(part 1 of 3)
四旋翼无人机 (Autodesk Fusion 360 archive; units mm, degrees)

design "基础版支架" references "摄像头", "舵机控制电板", "遥控天线", "画面图传电板", "摄像头与遥控接收电板", "螺旋桨"
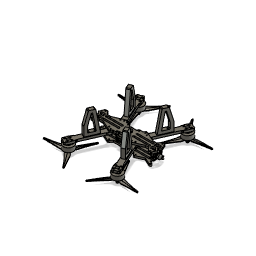
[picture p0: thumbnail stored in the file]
sketch "草图1" plane through (0, 0, 0) normal (0, 1, 0) x axis (1, 0, 0)
  line L1 (-87.5, 17.5) -> (87.5, 17.5)
  line L2 (-87.5, -17.5) -> (-87.5, 17.5)
  line L3 (87.5, -17.5) -> (-87.5, -17.5)
  line L4 (87.5, 17.5) -> (87.5, -17.5)
  line L5 (-87.5, -17.5) -> (87.5, 17.5)
  line L6 (87.5, -17.5) -> (-87.5, 17.5)
  line L7 (-15, 15) -> (15, 15)
  line L8 (-15, -15) -> (-15, 15)
  line L9 (15, -15) -> (-15, -15)
  line L10 (15, 15) -> (15, -15)
  line L11 (-15, -15) -> (15, 15)
  line L12 (15, -15) -> (-15, 15)
  line L13 (27.2129, 24) -> (22, 17.5)
  line L14 (42, 17.5) -> (27.2129, 24)
  line L15 (12, 17.5) -> (0, 17.5)
  line L16 (12, 12) -> (12, 17.5)
  line L17 (0, 12) -> (12, 12)
  line L18 (0, 17.5) -> (0, 12)
  line L19 (97, 0) -> (0, 0)
  line L20 (97, 40) -> (97, 0)
  line L21 (0, 40) -> (97, 40)
  line L22 (0, 0) -> (0, 40)
  line L23 (57.9246, 10.5) -> (42, 17.5)
  line L24 (67.6263, 10.5) -> (57.9246, 10.5)
  line L25 (73.5, 17.5) -> (67.6263, 10.5)
  line L26 (87.5, 6) -> (82.5, 17.5)
  line L27 (82.5, 1.8045) -> (87.5, 6)
  line L28 (82.5, 0) -> (82.5, 1.8045)
  circle C1 centre (-15, 15) radius 1.5
  circle C2 centre (-15, -15) radius 1.5
  circle C3 centre (15, -15) radius 1.5
  circle C4 centre (15, 15) radius 1.5
  point P6 (0, 0)
  point P1 (0, 0)
  point P11 (0, 0)
  point P8 (-15, 15)
  point P12 (-15, 15)
  point P16 (22, 17.5)
  point P18 (42, 17.5)
  point P21 (12, 12)
  point P19 (0, 17.5)
  point P23 (0, 0)
  point P29 (73.5, 17.5)
  point P30 (82.5, 17.5)
  point P31 (87.5, 6)
  point P33 (82.5, 0)
  point P2 (87.5, 17.5)
  point P3 (-87.5, 17.5)
  point P5 (87.5, -17.5)
  point P9 (-15, -15)
  point P10 (15, -15)
  point P22 (0, 12)
  point P17 (27.2129, 24)
  point P32 (82.5, 1.8045)
  horizontal L1
  perpendicular L1 L2
  parallel L1 L3
  parallel L2 L4
  coincident L5 P6
  coincident L6 P6
  coincident P1 P6
  horizontal L7
  perpendicular L7 L8
  parallel L7 L9
  parallel L8 L10
  coincident L11 P11
  coincident L12 P11
  coincident P1 P11
  coincident P8 P12
  coincident L1 P16
  coincident L1 P18
  horizontal L15
  vertical L16
  horizontal L17
  vertical L18
  coincident L11 P21
  midpoint L1 P19
  horizontal L19
  vertical L20
  horizontal L21
  vertical L22
  coincident P6 P23
  parallel L14 L23
  coincident L1 P29
  parallel L1 L24
  coincident L1 P30
  coincident L4 P31
  coincident L19 P33
  perpendicular L19 L28
  dimension "d1" distance P2 P3 = 175
  dimension "d2" distance P2 P5 = 35
  dimension "d3" distance P9 P10 = 30
  dimension "d4" distance P8 P9 = 30
  dimension "d5" diameter C1 = 3
  dimension "d8" angle L13 L14 = 105
  dimension "d9" distance P21 P22 = 12
  dimension "d10" distance P16 L22 = 22
  dimension "d11" distance P16 P18 = 20
  dimension "d12" distance L1 P17 = 6.5
  dimension "d13" distance L19 L24 = 10.5
  dimension "d14" angle L24 L25 = 130
  dimension "d15" distance L4 P29 = 14
  dimension "d16" distance P2 P30 = 5
  dimension "d17" distance L19 P31 = 6
  dimension "d18" distance L4 P32 = 5
  dimension "d19" angle L27 L28 = 130
  dimension "d7" C-Pattern1-Angle = 360
extrude "拉伸1" new body sketch "草图1" profile of L1 C4 L13 L14 L16 L17 L19 L22 L23 L24 L25 L26 L27 L28 along normal blind 2
sketch "草图2" plane through (0, 2, 0) normal (0, 1, 0) x axis (-1, 0, 0)
  line L1 (-73.5, -17.5) -> (-82.5, -17.5)
  line L2 (-67.6263, -10.5) -> (-73.5, -17.5)
  line L3 (-57.9246, -10.5) -> (-67.6263, -10.5)
  line L4 (-27.2129, -24) -> (-57.9246, -10.5)
  line L5 (-22, -17.5) -> (-27.2129, -24)
  line L6 (-12, -17.5) -> (-22, -17.5)
  line L7 (-12, -12) -> (-12, -17.5)
  line L8 (0, -12) -> (-12, -12)
  line L9 (0, 0) -> (0, -12)
  line L10 (-82.5, 0) -> (0, 0)
  line L11 (-82.5, -1.8045) -> (-82.5, 0)
  line L12 (-87.5, -6) -> (-82.5, -1.8045)
  line L13 (-82.5, -17.5) -> (-87.5, -6)
  circle C1 centre (-15, -15) radius 1.5
  circle C2 centre (-29, -18.845) radius 1.5
  circle C3 centre (-36.3237, -15.6258) radius 1.5
  point P16 (-29, -18.845)
  point P8 (-22, -17.5)
  point P17 (-36.3237, -15.6258)
  dimension "d22" diameter C2 = 3
  dimension "d23" diameter C3 = 3
  dimension "d24" distance L4 P16 = 4
  dimension "d25" distance P8 P16 = 7
  dimension "d26" distance L4 P17 = 4 (= "d24")
  dimension "d27" distance P16 P17 = 8
extrude "拉伸2" cut sketch "草图2" profile of C2 C3 against normal blind 5
sketch "草图3" plane through (0, 0, 0) normal (0, -1, 0) x axis (1, 0, 0)
  line L1 (82.5, -17.5) -> (73.5, -17.5)
  line L2 (87.5, -6) -> (82.5, -17.5)
  line L3 (82.5, -1.8045) -> (87.5, -6)
  line L4 (82.5, 0) -> (82.5, -1.8045)
  line L5 (0, 0) -> (82.5, 0)
  line L6 (0, -12) -> (0, 0)
  line L7 (12, -12) -> (0, -12)
  line L8 (12, -17.5) -> (12, -12)
  line L9 (22, -17.5) -> (12, -17.5)
  line L10 (27.2129, -24) -> (22, -17.5)
  line L11 (57.9246, -10.5) -> (27.2129, -24)
  line L12 (67.6263, -10.5) -> (57.9246, -10.5)
  line L13 (73.5, -17.5) -> (67.6263, -10.5)
  line L14 (64.3853, -7) -> (20, -7)
  line L15 (20, -3) -> (64.3853, -3)
  line L16 (64.3853, -5) -> (20, -5)
  circle C1 centre (29, -18.845) radius 1.5
  circle C2 centre (36.3237, -15.6258) radius 1.5
  circle C3 centre (15, -15) radius 1.5
  arc A1 centre (64.3853, -5) radius 2 clockwise from (64.3853, -3) to (64.3853, -7)
  arc A2 centre (20, -5) radius 2 clockwise from (20, -7) to (20, -3)
  tangent L14 A1
  tangent A1 L15
  parallel L14 L15
  tangent L15 A2
  tangent L14 A2
  parallel L5 L16
extrude "拉伸3" cut sketch "草图3" profile of L14 A1 L15 A2 against normal blind 8
sketch "草图4" plane through (0, 0, 0) normal (0, -1, 0) x axis (1, 0, 0)
  line L1 (20, -7) -> (64.3853, -7)
  line L2 (64.3853, -3) -> (20, -3)
  line L3 (82.5, -17.5) -> (73.5, -17.5)
  line L4 (87.5, -6) -> (82.5, -17.5)
  line L5 (82.5, -1.8045) -> (87.5, -6)
  line L6 (82.5, 0) -> (82.5, -1.8045)
  line L7 (0, 0) -> (82.5, 0)
  line L8 (0, -12) -> (0, 0)
  line L9 (12, -12) -> (0, -12)
  line L10 (12, -17.5) -> (12, -12)
  line L11 (22, -17.5) -> (12, -17.5)
  line L12 (27.2129, -24) -> (22, -17.5)
  line L13 (57.9246, -10.5) -> (27.2129, -24)
  line L14 (67.6263, -10.5) -> (57.9246, -10.5)
  line L15 (73.5, -17.5) -> (67.6263, -10.5)
  line L16 (70, -7.106) -> (70, -2)
  line L17 (72.4284, -10) -> (70, -7.106)
  line L18 (81.3992, -10) -> (72.4284, -10)
  line L19 (82.6408, -7.1443) -> (81.3992, -10)
  line L20 (78.5, -3.6697) -> (82.6408, -7.1443)
  line L21 (78.5, 0) -> (78.5, -3.6697)
  line L22 (78.5, -2) -> (70, -2)
  arc A1 centre (20, -5) radius 2 clockwise from (20, -7) to (20, -3)
  arc A2 centre (64.3853, -5) radius 2 clockwise from (64.3853, -3) to (64.3853, -7)
  circle C1 centre (29, -18.845) radius 1.5
  circle C2 centre (36.3237, -15.6258) radius 1.5
  circle C3 centre (15, -15) radius 1.5
  point P29 (78.5, 0)
  point P31 (78.5, -2)
  point P30 (70, -2)
  point P26 (81.3992, -10)
  perpendicular L7 L16
  parallel L7 L18
  coincident L7 P29
  perpendicular L7 L21
  parallel L15 L17
  parallel L4 L19
  parallel L5 L20
  perpendicular L21 L22
  coincident L21 P31
  dimension "d36" distance L4 L19 = 4
  dimension "d38" distance L15 L17 = 4 (= "d36")
  dimension "d39" distance L5 L20 = 4 (= "d36")
  dimension "d40" distance L6 L21 = 4 (= "d39")
  dimension "d47" distance L7 L22 = 2
  dimension "d48" distance P30 P31 = 8.5
  dimension "d74" distance P26 P29 = 10
extrude "拉伸4" cut sketch "草图4" profile of L7 L16 L17 L18 L19 L20 L21 against normal blind 6
fillet "圆角1" radius 2
sketch "草图5" plane through (0, 0, 0) normal (0, -1, 0) x axis (1, 0, 0)
  line L1 (20, -7) -> (64.3853, -7)
  line L2 (64.3853, -3) -> (20, -3)
  line L3 (22, -17.5) -> (14, -17.5)
  line L4 (27.2129, -24) -> (22, -17.5)
  line L5 (57.9246, -10.5) -> (27.2129, -24)
  line L6 (67.6263, -10.5) -> (57.9246, -10.5)
  line L7 (73.5, -17.5) -> (67.6263, -10.5)
  line L8 (82.5, -17.5) -> (73.5, -17.5)
  line L9 (87.5, -6) -> (82.5, -17.5)
  line L10 (82.5, -1.8045) -> (87.5, -6)
  line L11 (82.5, 0) -> (82.5, -1.8045)
  line L12 (78.5, -3.6697) -> (78.5, -2)
  line L13 (82.6408, -7.1443) -> (78.5, -3.6697)
  line L14 (81.3992, -10) -> (82.6408, -7.1443)
  line L15 (72.4284, -10) -> (81.3992, -10)
  line L16 (70, -7.106) -> (72.4284, -10)
  line L17 (70, -2) -> (70, -7.106)
  line L18 (0, 0) -> (82.5, 0)
  line L19 (0, -12) -> (0, 0)
  line L20 (10, -12) -> (0, -12)
  line L21 (12, -15.5) -> (12, -14)
  line L22 (78.5, -2) -> (70, -2)
  arc A1 centre (20, -5) radius 2 clockwise from (20, -7) to (20, -3)
  arc A2 centre (64.3853, -5) radius 2 clockwise from (64.3853, -3) to (64.3853, -7)
  circle C1 centre (29, -18.845) radius 1.5
  circle C2 centre (36.3237, -15.6258) radius 1.5
  circle C3 centre (15, -15) radius 1.5
  arc A3 centre (14, -15.5) radius 2 clockwise from (14, -17.5) to (12, -15.5)
  arc A4 centre (10, -14) radius 2 clockwise from (10, -12) to (12, -14)
  circle C4 centre (0, 0) radius 9.434
  point P30 (0, 0)
  point P35 (0, 0)
  coincident P30 P35
extrude "拉伸5" cut sketch "草图5" profile of L18 L19 C4 against normal blind 11
fillet "圆角2" radius 2.5
extrude "拉伸6" add of existing geometry blind 2
sketch "草图6" plane through (0, 0, 0) normal (0, -1, 0) x axis (1, 0, 0)
  line L1 (70, -2) -> (70, -7.106)
  line L2 (78.5, -2) -> (70, -2)
  line L3 (78.5, -3.6697) -> (78.5, -2)
  line L4 (82.6408, -7.1443) -> (78.5, -3.6697)
  line L5 (81.3992, -10) -> (82.6408, -7.1443)
  line L6 (72.4284, -10) -> (81.3992, -10)
  line L7 (70, -7.106) -> (72.4284, -10)
  line L8 (20, -7) -> (64.3853, -7)
  line L9 (64.3853, -3) -> (20, -3)
  line L10 (57.9246, -10.5) -> (28.969, -23.2281)
  line L11 (67.6263, -10.5) -> (57.9246, -10.5)
  line L12 (73.5, -17.5) -> (67.6263, -10.5)
  line L13 (73.5, -19.5) -> (73.5, -17.5)
  line L14 (82.5, -19.5) -> (73.5, -19.5)
  line L15 (82.5, -17.5) -> (82.5, -19.5)
  line L16 (87.5, -6) -> (82.5, -17.5)
  line L17 (82.5, -1.8045) -> (87.5, -6)
  line L18 (82.5, 0) -> (82.5, -1.8045)
  line L19 (9.434, 0) -> (82.5, 0)
  line L20 (0, -12) -> (0, -9.434)
  line L21 (10, -12) -> (0, -12)
  line L22 (12, -15.5) -> (12, -14)
  line L23 (20.8003, -17.5) -> (14, -17.5)
  line L24 (26.0127, -22.5035) -> (22.7506, -18.4359)
  arc A1 centre (20, -5) radius 2 clockwise from (20, -7) to (20, -3)
  arc A2 centre (64.3853, -5) radius 2 clockwise from (64.3853, -3) to (64.3853, -7)
  circle C1 centre (29, -18.845) radius 1.5
  circle C2 centre (36.3237, -15.6258) radius 1.5
  circle C3 centre (15, -15) radius 1.5
  arc A3 centre (27.963, -20.9394) radius 2.5 clockwise from (28.969, -23.2281) to (26.0127, -22.5035)
  arc A4 centre (0, 0) radius 9.434 clockwise from (9.434, 0) to (0, -9.434)
  arc A5 centre (10, -14) radius 2 clockwise from (10, -12) to (12, -14)
  arc A6 centre (14, -15.5) radius 2 clockwise from (14, -17.5) to (12, -15.5)
  arc A7 centre (20.8003, -20) radius 2.5 clockwise from (20.8003, -17.5) to (22.7506, -18.4359)
  circle C4 centre (77.9376, -16.5656) radius 1.5
  dimension "d54" diameter C4 = 3
extrude "拉伸7" cut sketch "草图6" profile of C4 against normal blind 6
fillet "圆角3" radius 1
sketch "草图10" plane through (0, 0, 0) normal (0, -1, 0) x axis (1, 0, 0)
  line L1 (70, -2) -> (70, -7.106)
  line L2 (78.5, -2) -> (70, -2)
  line L3 (78.5, -3.6697) -> (78.5, -2)
  line L4 (82.6408, -7.1443) -> (78.5, -3.6697)
  line L5 (81.3992, -10) -> (82.6408, -7.1443)
  line L6 (72.4284, -10) -> (81.3992, -10)
  line L7 (70, -7.106) -> (72.4284, -10)
  line L8 (20, -7) -> (64.3853, -7)
  line L9 (64.3853, -3) -> (20, -3)
  line L10 (82.5, -17.5) -> (82.5, -18.5)
  line L11 (87.5, -6) -> (82.5, -17.5)
  line L12 (82.5, -1.8045) -> (87.5, -6)
  line L13 (82.5, 0) -> (82.5, -1.8045)
  line L14 (9.434, 0) -> (82.5, 0)
  line L15 (0, -12) -> (0, -9.434)
  line L16 (10, -12) -> (0, -12)
  line L17 (12, -15.5) -> (12, -14)
  line L18 (20.8003, -17.5) -> (14, -17.5)
  line L19 (26.0127, -22.5035) -> (22.7506, -18.4359)
  line L20 (57.9246, -10.5) -> (28.969, -23.2281)
  line L21 (67.6263, -10.5) -> (57.9246, -10.5)
  line L22 (73.5, -17.5) -> (67.6263, -10.5)
  line L23 (73.5, -18.5) -> (73.5, -17.5)
  line L24 (81.5, -19.5) -> (74.5, -19.5)
  line L25 (81.3992, -10) -> (72.4284, -10)
  line L26 (81.3992, -12) -> (81.3992, -10)
  line L27 (72.4284, -12) -> (81.3992, -12)
  line L28 (72.4284, -10) -> (72.4284, -12)
  circle C1 centre (77.9376, -16.5656) radius 1.5
  arc A1 centre (20, -5) radius 2 clockwise from (20, -7) to (20, -3)
  arc A2 centre (64.3853, -5) radius 2 clockwise from (64.3853, -3) to (64.3853, -7)
  circle C2 centre (29, -18.845) radius 1.5
  circle C3 centre (36.3237, -15.6258) radius 1.5
  circle C4 centre (15, -15) radius 1.5
  arc A3 centre (81.5, -18.5) radius 1 clockwise from (82.5, -18.5) to (81.5, -19.5)
  arc A4 centre (0, 0) radius 9.434 clockwise from (9.434, 0) to (0, -9.434)
  arc A5 centre (10, -14) radius 2 clockwise from (10, -12) to (12, -14)
  arc A6 centre (14, -15.5) radius 2 clockwise from (14, -17.5) to (12, -15.5)
  arc A7 centre (20.8003, -20) radius 2.5 clockwise from (20.8003, -17.5) to (22.7506, -18.4359)
  arc A8 centre (27.963, -20.9394) radius 2.5 clockwise from (28.969, -23.2281) to (26.0127, -22.5035)
  arc A9 centre (74.5, -18.5) radius 1 clockwise from (74.5, -19.5) to (73.5, -18.5)
  point P9 (72.4284, -10)
  point P48 (72.4284, -10)
  point P8 (81.3992, -10)
  point P49 (81.3992, -10)
  point P50 (81.3992, -12)
  horizontal L25
  vertical L26
  horizontal L27
  vertical L28
  coincident P9 P48
  coincident P8 P49
  dimension "d75" distance P49 P50 = 2
extrude "拉伸12" add sketch "草图10" profile of L6 L25 L26 L27 L28 along normal blind 15
sketch "草图11" plane through (0, 0, -12) normal (0, 0, -1) x axis (-1, 0, 0)
  line L1 (-81.3992, 0) -> (-72.4284, 0)
  line L2 (-81.3992, -15) -> (-81.3992, 0)
  line L3 (-72.4284, -15) -> (-81.3992, -15)
  line L4 (-72.4284, 0) -> (-72.4284, -15)
  line L5 (-72.4284, 0) -> (-76.9138, -15)
  line L6 (-77.1774, -10.3836) -> (-78.0369, -13.2578)
  line L7 (-79.7614, -12.7422) -> (-78.902, -9.8679)
  line L8 (-78.0397, -10.1258) -> (-78.8992, -13)
  arc A1 centre (-78.0397, -10.1258) radius 0.9 clockwise from (-78.902, -9.8679) to (-77.1774, -10.3836)
  arc A2 centre (-78.8992, -13) radius 0.9 clockwise from (-78.0369, -13.2578) to (-79.7614, -12.7422)
  point P6 (-76.9138, -15)
  point P2 (-72.4284, 0)
  point P7 (-72.4284, 0)
  point P12 (-78.8992, -13)
  point P13 (-78.0397, -10.1258)
  midpoint L3 P6
  coincident P2 P7
  tangent L6 A1
  tangent A1 L7
  parallel L6 L7
  tangent L7 A2
  tangent L6 A2
  parallel L5 L6
  dimension "d78" distance L6 L7 = 1.8
  dimension "d79" distance P12 P13 = 3
  dimension "d80" distance L1 P12 = 13
  dimension "d81" distance L2 P12 = 2.5
extrude "拉伸13" cut sketch "草图11" profile of L3 L4 L5 L6 A1 L7 A2 against normal blind 4
mirror "镜像1" mirrorStitchTolerance 0.1
mirror "镜像2" mirrorStitchTolerance 0.1
work_plane "工作平面" AlongDistance -29
sketch "草图7" plane through (0, -27, 0) normal (0, 1, 0) x axis (1, 0, 0)
  line L1 (0, -12) -> (0, 0)
  line L2 (28.1101, -12) -> (0, -12)
  line L3 (34.9916, -20.5807) -> (28.1101, -12)
  line L4 (57.9246, -10.5) -> (34.9916, -20.5807)
  line L5 (26.0127, -22.5035) -> (22.7506, -18.4359)
  line L6 (57.9246, -10.5) -> (28.969, -23.2281)
  line L7 (10, -12) -> (-10, -12)
  line L8 (76.7008, -19.2266) -> (57.9246, -10.5)
  line L9 (71.8492, -10.5) -> (79.1743, -13.9045)
  line L10 (74.5, -19.5) -> (81.5, -19.5)
  line L11 (71.8492, 0) -> (71.8492, -10.5)
  line L12 (0, 0) -> (71.8492, 0)
  line L13 (64.3853, -3) -> (20, -3)
  line L14 (-64.3853, 7) -> (-20, 7)
  line L15 (-20, 3) -> (-64.3853, 3)
  line L16 (-70, 7.106) -> (-70, 2)
  line L17 (-72.4284, 10) -> (-70, 7.106)
  line L18 (-82.6408, 7.1443) -> (-81.3992, 10)
  line L19 (-78.5, 3.6697) -> (-82.6408, 7.1443)
  line L20 (-78.5, 2) -> (-78.5, 3.6697)
  line L21 (-70, 2) -> (-78.5, 2)
  line L22 (-70, -2) -> (-70, -7.106)
  line L23 (-78.5, -2) -> (-70, -2)
  line L24 (-78.5, -3.6697) -> (-78.5, -2)
  line L25 (-82.6408, -7.1443) -> (-78.5, -3.6697)
  line L26 (-81.3992, -10) -> (-82.6408, -7.1443)
  line L27 (-70, -7.106) -> (-72.4284, -10)
  line L28 (-20, -7) -> (-64.3853, -7)
  line L29 (-64.3853, -3) -> (-20, -3)
  line L30 (64.3853, -7) -> (20, -7)
  line L31 (20, -3) -> (64.3853, -3)
  line L32 (70, -7.106) -> (70, -2)
  line L33 (72.4284, -10) -> (70, -7.106)
  line L34 (82.6408, -7.1443) -> (81.3992, -10)
  line L35 (78.5, -3.6697) -> (82.6408, -7.1443)
  line L36 (78.5, -2) -> (78.5, -3.6697)
  line L37 (70, -2) -> (78.5, -2)
  line L38 (70, 2) -> (70, 7.106)
  line L39 (78.5, 2) -> (70, 2)
  line L40 (78.5, 3.6697) -> (78.5, 2)
  line L41 (82.6408, 7.1443) -> (78.5, 3.6697)
  line L42 (81.3992, 10) -> (82.6408, 7.1443)
  line L43 (70, 7.106) -> (72.4284, 10)
  line L44 (20, 7) -> (64.3853, 7)
  line L45 (64.3853, 3) -> (20, 3)
  line L46 (-10, -12) -> (10, -12)
  line L47 (-12, -15.5) -> (-12, -14)
  line L48 (-20.8003, -17.5) -> (-14, -17.5)
  line L49 (-26.0127, -22.5035) -> (-22.7506, -18.4359)
  line L50 (-57.9246, -10.5) -> (-28.969, -23.2281)
  line L51 (-67.6263, -10.5) -> (-57.9246, -10.5)
  line L52 (-73.5, -17.5) -> (-67.6263, -10.5)
  line L53 (-73.5, -18.5) -> (-73.5, -17.5)
  line L54 (-81.5, -19.5) -> (-74.5, -19.5)
  line L55 (-82.5, -17.5) -> (-82.5, -18.5)
  line L56 (-87.5, -6) -> (-82.5, -17.5)
  line L57 (-82.5, -1.8045) -> (-87.5, -6)
  line L58 (-82.5, 1.8045) -> (-82.5, -1.8045)
  line L59 (-87.5, 6) -> (-82.5, 1.8045)
  line L60 (-82.5, 17.5) -> (-87.5, 6)
  line L61 (-82.5, 18.5) -> (-82.5, 17.5)
  line L62 (-74.5, 19.5) -> (-81.5, 19.5)
  line L63 (-73.5, 17.5) -> (-73.5, 18.5)
  line L64 (-67.6263, 10.5) -> (-73.5, 17.5)
  line L65 (-57.9246, 10.5) -> (-67.6263, 10.5)
  line L66 (-28.969, 23.2281) -> (-57.9246, 10.5)
  line L67 (-22.7506, 18.4359) -> (-26.0127, 22.5035)
  line L68 (-14, 17.5) -> (-20.8003, 17.5)
  line L69 (-12, 14) -> (-12, 15.5)
  line L70 (10, 12) -> (-10, 12)
  line L71 (12, 15.5) -> (12, 14)
  line L72 (20.8003, 17.5) -> (14, 17.5)
  line L73 (26.0127, 22.5035) -> (22.7506, 18.4359)
  line L74 (57.9246, 10.5) -> (28.969, 23.2281)
  line L75 (67.6263, 10.5) -> (57.9246, 10.5)
  line L76 (73.5, 17.5) -> (67.6263, 10.5)
  line L77 (73.5, 18.5) -> (73.5, 17.5)
  line L78 (81.5, 19.5) -> (74.5, 19.5)
  line L79 (82.5, 17.5) -> (82.5, 18.5)
  line L80 (87.5, 6) -> (82.5, 17.5)
  line L81 (82.5, 1.8045) -> (87.5, 6)
  line L82 (82.5, -1.8045) -> (82.5, 1.8045)
  line L83 (87.5, -6) -> (82.5, -1.8045)
  line L84 (82.5, -17.5) -> (87.5, -6)
  line L85 (82.5, -18.5) -> (82.5, -17.5)
  line L86 (74.5, -19.5) -> (81.5, -19.5)
  line L87 (73.5, -17.5) -> (73.5, -18.5)
  line L88 (67.6263, -10.5) -> (73.5, -17.5)
  line L89 (57.9246, -10.5) -> (67.6263, -10.5)
  line L90 (28.969, -23.2281) -> (57.9246, -10.5)
  line L91 (22.7506, -18.4359) -> (26.0127, -22.5035)
  line L92 (14, -17.5) -> (20.8003, -17.5)
  line L93 (12, -14) -> (12, -15.5)
  line L94 (20, -7) -> (64.3853, -7)
  line L95 (-81.3992, 10) -> (-81.3992, 12)
  line L96 (-72.4284, 12) -> (-72.4284, 10)
  line L97 (-81.3992, 12) -> (-72.4284, 12)
  line L98 (-81.3992, -12) -> (-81.3992, -10)
  line L99 (-72.4284, -12) -> (-81.3992, -12)
  line L100 (-72.4284, -10) -> (-72.4284, -12)
  line L101 (81.3992, -10) -> (81.3992, -12)
  line L102 (72.4284, -12) -> (72.4284, -10)
  line L103 (81.3992, -12) -> (72.4284, -12)
  line L104 (81.3992, 12) -> (81.3992, 10)
  line L105 (72.4284, 12) -> (81.3992, 12)
  line L106 (72.4284, 10) -> (72.4284, 12)
  arc A1 centre (77.9376, -16.5656) radius 2.9344 clockwise from (79.1743, -13.9045) to (76.7008, -19.2266)
  circle C1 centre (77.9376, -16.5656) radius 1.5
  circle C2 centre (0, 0) radius 9.434
  arc A2 centre (64.3853, -5) radius 2 clockwise from (64.3853, -3) to (64.3853, -7)
  circle C3 centre (0, 0) radius 9.434
  circle C4 centre (-15, 15) radius 1.5
  circle C5 centre (-36.3237, 15.6258) radius 1.5
  circle C6 centre (-29, 18.845) radius 1.5
  arc A3 centre (-64.3853, 5) radius 2 clockwise from (-64.3853, 3) to (-64.3853, 7)
  arc A4 centre (-20, 5) radius 2 clockwise from (-20, 7) to (-20, 3)
  circle C7 centre (-77.9376, 16.5656) radius 1.5
  circle C8 centre (-77.9376, -16.5656) radius 1.5
  arc A5 centre (-20, -5) radius 2 clockwise from (-20, -3) to (-20, -7)
  arc A6 centre (-64.3853, -5) radius 2 clockwise from (-64.3853, -7) to (-64.3853, -3)
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  point P1 (0, 0)
  point P2 (0, 0)
  point P6 (57.9246, -10.5)
  point P3 (0, -12)
  point P10 (57.9246, -10.5)
  point P21 (0, 0)
  point P16 (71.8492, -10.5)
  coincident P1 P2
  vertical L1
  perpendicular L1 L2
  parallel L3 L5
  parallel L4 L6
  coincident P6 L6
  coincident P3 L7
  tangent L8 A1
  tangent A1 L9
  concentric A1 C1
  tangent A1 L10
  coincident P6 P10
  parallel L8 L9
  vertical L11
  coincident P1 P21
  perpendicular L1 L12
  horizontal P6 P16
extrude "拉伸8" new body sketch "草图7" along normal blind 2
fillet "圆角4" radius 2.5
mirror "镜像3" mirrorStitchTolerance 0.1
mirror "镜像4" mirrorStitchTolerance 0.1
sketch "草图8" plane through (0, -27, 0) normal (0, -1, 0) x axis (1, 0, 0)
  line L1 (28.1101, -12) -> (-28.1101, -12)
  line L2 (33.7914, -19.0842) -> (28.1101, -12)
  line L3 (57.9246, -10.5) -> (36.7477, -19.8087)
  line L4 (76.7008, -19.2266) -> (57.9246, -10.5)
  line L5 (71.8492, -10.5) -> (79.1743, -13.9045)
  line L6 (71.8492, -9.3097) -> (71.8492, -10.5)
  line L7 (70, -7.106) -> (71.8492, -9.3097)
  line L8 (70, -2) -> (70, -7.106)
  line L9 (71.8492, -2) -> (70, -2)
  line L10 (71.8492, 2) -> (71.8492, -2)
  line L11 (70, 2) -> (71.8492, 2)
  line L12 (70, 7.106) -> (70, 2)
  line L13 (71.8492, 9.3097) -> (70, 7.106)
  line L14 (71.8492, 10.5) -> (71.8492, 9.3097)
  line L15 (79.1743, 13.9045) -> (71.8492, 10.5)
  line L16 (57.9246, 10.5) -> (76.7008, 19.2266)
  line L17 (36.7477, 19.8087) -> (57.9246, 10.5)
  line L18 (28.1101, 12) -> (33.7914, 19.0842)
  line L19 (-28.1101, 12) -> (28.1101, 12)
  line L20 (-33.7914, 19.0842) -> (-28.1101, 12)
  line L21 (-57.9246, 10.5) -> (-36.7477, 19.8087)
  line L22 (-76.7008, 19.2266) -> (-57.9246, 10.5)
  line L23 (-71.8492, 10.5) -> (-79.1743, 13.9045)
  line L24 (-71.8492, 9.3097) -> (-71.8492, 10.5)
  line L25 (-70, 7.106) -> (-71.8492, 9.3097)
  line L26 (-70, 2) -> (-70, 7.106)
  line L27 (-71.8492, 2) -> (-70, 2)
  line L28 (-71.8492, -2) -> (-71.8492, 2)
  line L29 (-70, -2) -> (-71.8492, -2)
  line L30 (-70, -7.106) -> (-70, -2)
  line L31 (-71.8492, -9.3097) -> (-70, -7.106)
  line L32 (-71.8492, -10.5) -> (-71.8492, -9.3097)
  line L33 (-79.1743, -13.9045) -> (-71.8492, -10.5)
  line L34 (-57.9246, -10.5) -> (-76.7008, -19.2266)
  line L35 (-36.7477, -19.8087) -> (-57.9246, -10.5)
  line L36 (-28.1101, -12) -> (-33.7914, -19.0842)
  line L37 (-20, 7) -> (-64.3853, 7)
  line L38 (-64.3853, 3) -> (-20, 3)
  line L39 (-20, -3) -> (-64.3853, -3)
  line L40 (-64.3853, -7) -> (-20, -7)
  line L41 (20, -7) -> (64.3853, -7)
  line L42 (64.3853, -3) -> (20, -3)
  line L43 (20, 3) -> (64.3853, 3)
  line L44 (64.3853, 7) -> (20, 7)
  line L45 (-68.2889, 13.4715) -> (-74.6684, 13.4715)
  line L46 (-68.2889, -12.4599) -> (-68.2889, 13.4715)
  line L47 (-74.6684, -12.4599) -> (-68.2889, -12.4599)
  line L48 (-74.6684, 13.4715) -> (-74.6684, -12.4599)
  arc A1 centre (35.7417, -17.5201) radius 2.5 clockwise from (36.7477, -19.8087) to (33.7914, -19.0842)
  arc A2 centre (77.9376, -16.5656) radius 2.9344 clockwise from (79.1743, -13.9045) to (76.7008, -19.2266)
  arc A3 centre (77.9376, 16.5656) radius 2.9344 clockwise from (76.7008, 19.2266) to (79.1743, 13.9045)
  arc A4 centre (35.7417, 17.5201) radius 2.5 clockwise from (33.7914, 19.0842) to (36.7477, 19.8087)
  arc A5 centre (-35.7417, 17.5201) radius 2.5 clockwise from (-36.7477, 19.8087) to (-33.7914, 19.0842)
  arc A6 centre (-77.9376, 16.5656) radius 2.9344 clockwise from (-79.1743, 13.9045) to (-76.7008, 19.2266)
  arc A7 centre (-77.9376, -16.5656) radius 2.9344 clockwise from (-76.7008, -19.2266) to (-79.1743, -13.9045)
  arc A8 centre (-35.7417, -17.5201) radius 2.5 clockwise from (-33.7914, -19.0842) to (-36.7477, -19.8087)
  circle C1 centre (-77.9376, 16.5656) radius 1.5
  circle C2 centre (-36.3237, 15.6258) radius 1.5
  arc A9 centre (-64.3853, 5) radius 2 clockwise from (-64.3853, 3) to (-64.3853, 7)
  arc A10 centre (-20, 5) radius 2 clockwise from (-20, 7) to (-20, 3)
  arc A11 centre (-64.3853, -5) radius 2 clockwise from (-64.3853, -7) to (-64.3853, -3)
  arc A12 centre (-20, -5) radius 2 clockwise from (-20, -3) to (-20, -7)
  circle C3 centre (-36.3237, -15.6258) radius 1.5
  circle C4 centre (-77.9376, -16.5656) radius 1.5
  circle C5 centre (77.9376, -16.5656) radius 1.5
  circle C6 centre (36.3237, -15.6258) radius 1.5
  arc A13 centre (64.3853, -5) radius 2 clockwise from (64.3853, -3) to (64.3853, -7)
  arc A14 centre (20, -5) radius 2 clockwise from (20, -7) to (20, -3)
  circle C7 centre (0, 0) radius 9.434
  arc A15 centre (64.3853, 5) radius 2 clockwise from (64.3853, 7) to (64.3853, 3)
  arc A16 centre (20, 5) radius 2 clockwise from (20, 3) to (20, 7)
  circle C8 centre (36.3237, 15.6258) radius 1.5
  circle C9 centre (77.9376, 16.5656) radius 1.5
  horizontal L45
  vertical L46
  horizontal L47
  vertical L48
extrude "拉伸9" add sketch "草图8" profile of L23 L24 L25 L26 L27 L28 L29 L30 L31 L32 L33 L48 against normal blind 2
sketch "草图9" plane through (0, -27, 0) normal (0, -1, 0) x axis (1, 0, 0)
  line L1 (28.1101, -12) -> (-28.1101, -12)
  line L2 (33.7914, -19.0842) -> (28.1101, -12)
  line L3 (57.9246, -10.5) -> (36.7477, -19.8087)
  line L4 (76.7008, -19.2266) -> (57.9246, -10.5)
  line L5 (71.8492, -10.5) -> (79.1743, -13.9045)
  line L6 (71.8492, -9.3097) -> (71.8492, -10.5)
  line L7 (70, -7.106) -> (71.8492, -9.3097)
  line L8 (70, -2) -> (70, -7.106)
  line L9 (71.8492, -2) -> (70, -2)
  line L10 (71.8492, 2) -> (71.8492, -2)
  line L11 (70, 2) -> (71.8492, 2)
  line L12 (70, 7.106) -> (70, 2)
  line L13 (71.8492, 9.3097) -> (70, 7.106)
  line L14 (71.8492, 10.5) -> (71.8492, 9.3097)
  line L15 (79.1743, 13.9045) -> (71.8492, 10.5)
  line L16 (57.9246, 10.5) -> (76.7008, 19.2266)
  line L17 (36.7477, 19.8087) -> (57.9246, 10.5)
  line L18 (28.1101, 12) -> (33.7914, 19.0842)
  line L19 (-28.1101, 12) -> (28.1101, 12)
  line L20 (-33.7914, 19.0842) -> (-28.1101, 12)
  line L21 (-57.9246, 10.5) -> (-36.7477, 19.8087)
  line L22 (-76.7008, 19.2266) -> (-57.9246, 10.5)
  line L23 (-74.6684, 11.8103) -> (-79.1743, 13.9045)
  line L24 (-74.6684, -11.8103) -> (-74.6684, 11.8103)
  line L25 (-79.1743, -13.9045) -> (-74.6684, -11.8103)
  line L26 (-57.9246, -10.5) -> (-76.7008, -19.2266)
  line L27 (-36.7477, -19.8087) -> (-57.9246, -10.5)
  line L28 (-28.1101, -12) -> (-33.7914, -19.0842)
  line L29 (-20, 7) -> (-64.3853, 7)
  line L30 (-64.3853, 3) -> (-20, 3)
  line L31 (-20, -3) -> (-64.3853, -3)
  line L32 (-64.3853, -7) -> (-20, -7)
  line L33 (20, -7) -> (64.3853, -7)
  line L34 (64.3853, -3) -> (20, -3)
  line L35 (20, 3) -> (64.3853, 3)
  line L36 (64.3853, 7) -> (20, 7)
  line L37 (-77.4594, 5.9999) -> (-74.6684, 7.6476)
  line L38 (-77.4594, -5.9999) -> (-77.4594, 5.9999)
  line L39 (-74.6684, -7.6476) -> (-77.4594, -5.9999)
  arc A1 centre (35.7417, -17.5201) radius 2.5 clockwise from (36.7477, -19.8087) to (33.7914, -19.0842)
  arc A2 centre (77.9376, -16.5656) radius 2.9344 clockwise from (79.1743, -13.9045) to (76.7008, -19.2266)
  arc A3 centre (77.9376, 16.5656) radius 2.9344 clockwise from (76.7008, 19.2266) to (79.1743, 13.9045)
  arc A4 centre (35.7417, 17.5201) radius 2.5 clockwise from (33.7914, 19.0842) to (36.7477, 19.8087)
  arc A5 centre (-35.7417, 17.5201) radius 2.5 clockwise from (-36.7477, 19.8087) to (-33.7914, 19.0842)
  arc A6 centre (-77.9376, 16.5656) radius 2.9344 clockwise from (-79.1743, 13.9045) to (-76.7008, 19.2266)
  arc A7 centre (-77.9376, -16.5656) radius 2.9344 clockwise from (-76.7008, -19.2266) to (-79.1743, -13.9045)
  arc A8 centre (-35.7417, -17.5201) radius 2.5 clockwise from (-33.7914, -19.0842) to (-36.7477, -19.8087)
  circle C1 centre (-77.9376, 16.5656) radius 1.5
  circle C2 centre (-36.3237, 15.6258) radius 1.5
  arc A9 centre (-64.3853, 5) radius 2 clockwise from (-64.3853, 3) to (-64.3853, 7)
  arc A10 centre (-20, 5) radius 2 clockwise from (-20, 7) to (-20, 3)
  arc A11 centre (-64.3853, -5) radius 2 clockwise from (-64.3853, -7) to (-64.3853, -3)
  arc A12 centre (-20, -5) radius 2 clockwise from (-20, -3) to (-20, -7)
  circle C3 centre (-36.3237, -15.6258) radius 1.5
  circle C4 centre (-77.9376, -16.5656) radius 1.5
  circle C5 centre (77.9376, -16.5656) radius 1.5
  circle C6 centre (36.3237, -15.6258) radius 1.5
  arc A13 centre (64.3853, -5) radius 2 clockwise from (64.3853, -3) to (64.3853, -7)
  arc A14 centre (20, -5) radius 2 clockwise from (20, -7) to (20, -3)
  circle C7 centre (0, 0) radius 9.434
  arc A15 centre (64.3853, 5) radius 2 clockwise from (64.3853, 7) to (64.3853, 3)
  arc A16 centre (20, 5) radius 2 clockwise from (20, 3) to (20, 7)
  circle C8 centre (36.3237, 15.6258) radius 1.5
  circle C9 centre (77.9376, 16.5656) radius 1.5
  circle C10 centre (-71, 0) radius 4.5
  point P76 (-74.6684, 7.6476)
  point P79 (-74.6684, -7.6476)
  point P80 (-77.4594, 0)
  point P81 (-74.6684, 0)
  coincident L24 P76
  parallel L24 L38
  coincident L24 P79
  midpoint L38 P80
  midpoint L24 P81
  horizontal P80 P81
  equal L37 L39
  dimension "d69" diameter C10 = 9
extrude "拉伸10" add sketch "草图9" profile of L24 C10 L37 L38 L39 against normal blind 2
extrude "拉伸11" cut sketch "草图9" profile of L24 C10 against normal blind 3
fillet "圆角5" radius 2.75
sketch "草图12" plane through (0, 0, -12) normal (0, 0, -1) x axis (-1, 0, 0)
  line L1 (76.9138, -15) -> (72.4284, 0)
  line L2 (81.3992, -15) -> (76.9138, -15)
  line L3 (81.3992, 0) -> (81.3992, -15)
  line L4 (72.4284, 0) -> (81.3992, 0)
  line L5 (77.1774, -10.3836) -> (78.0369, -13.2578)
  line L6 (79.7614, -12.7422) -> (78.902, -9.8679)
  arc A1 centre (78.0397, -10.1258) radius 0.9 clockwise from (77.1774, -10.3836) to (78.902, -9.8679)
  arc A2 centre (78.8992, -13) radius 0.9 clockwise from (79.7614, -12.7422) to (78.0369, -13.2578)
extrude "拉伸14" cut sketch "草图12" against normal blind 70
sketch "草图13" plane through (0, 0, 0) normal (0, -1, 0) x axis (1, 0, 0)
  line L1 (-70, 7.106) -> (-72.4284, 10)
  line L2 (-70, 2) -> (-70, 7.106)
  line L3 (-78.5, 2) -> (-70, 2)
  line L4 (-78.5, 3.6697) -> (-78.5, 2)
  line L5 (-82.6408, 7.1443) -> (-78.5, 3.6697)
  line L6 (-81.3992, 10) -> (-82.6408, 7.1443)
  line L7 (-72.4284, 10) -> (-81.3992, 10)
  line L8 (-70, -2) -> (-78.5, -2)
  line L9 (-70, -7.106) -> (-70, -2)
  line L10 (-72.4284, -10) -> (-70, -7.106)
  line L11 (-81.3992, -10) -> (-72.4284, -10)
  line L12 (-82.6408, -7.1443) -> (-81.3992, -10)
  line L13 (-78.5, -3.6697) -> (-82.6408, -7.1443)
  line L14 (-78.5, -2) -> (-78.5, -3.6697)
  line L15 (81.3992, -12) -> (81.3992, -10)
  line L16 (72.4284, -12) -> (81.3992, -12)
  line L17 (72.4284, -10) -> (72.4284, -12)
  line L18 (70, -7.106) -> (72.4284, -10)
  line L19 (70, -2) -> (70, -7.106)
  line L20 (78.5, -2) -> (70, -2)
  line L21 (78.5, -3.6697) -> (78.5, -2)
  line L22 (82.6408, -7.1443) -> (78.5, -3.6697)
  line L23 (81.3992, -10) -> (82.6408, -7.1443)
  line L24 (20, -7) -> (64.3853, -7)
  line L25 (64.3853, -3) -> (20, -3)
  line L26 (64.3853, 7) -> (20, 7)
  line L27 (20, 3) -> (64.3853, 3)
  line L28 (81.3992, 10) -> (81.3992, 12)
  line L29 (82.6408, 7.1443) -> (81.3992, 10)
  line L30 (78.5, 3.6697) -> (82.6408, 7.1443)
  line L31 (78.5, 2) -> (78.5, 3.6697)
  line L32 (70, 2) -> (78.5, 2)
  line L33 (70, 7.106) -> (70, 2)
  line L34 (72.4284, 10) -> (70, 7.106)
  line L35 (72.4284, 12) -> (72.4284, 10)
  line L36 (81.3992, 12) -> (72.4284, 12)
  line L37 (-20, 7) -> (-64.3853, 7)
  line L38 (-64.3853, 3) -> (-20, 3)
  line L39 (-64.3853, -7) -> (-20, -7)
  line L40 (-20, -3) -> (-64.3853, -3)
  line L41 (-73.5, 17.5) -> (-67.6263, 10.5)
  line L42 (-73.5, 18.5) -> (-73.5, 17.5)
  line L43 (-81.5, 19.5) -> (-74.5, 19.5)
  line L44 (-82.5, 17.5) -> (-82.5, 18.5)
  line L45 (-87.5, 6) -> (-82.5, 17.5)
  line L46 (-82.5, 1.8045) -> (-87.5, 6)
  line L47 (-82.5, -1.8045) -> (-82.5, 1.8045)
  line L48 (-87.5, -6) -> (-82.5, -1.8045)
  line L49 (-82.5, -17.5) -> (-87.5, -6)
  line L50 (-82.5, -18.5) -> (-82.5, -17.5)
  line L51 (-74.5, -19.5) -> (-81.5, -19.5)
  line L52 (-73.5, -17.5) -> (-73.5, -18.5)
  line L53 (-67.6263, -10.5) -> (-73.5, -17.5)
  line L54 (-57.9246, -10.5) -> (-67.6263, -10.5)
  line L55 (-28.969, -23.2281) -> (-57.9246, -10.5)
  line L56 (-22.7506, -18.4359) -> (-26.0127, -22.5035)
  line L57 (-14, -17.5) -> (-20.8003, -17.5)
  line L58 (-12, -14) -> (-12, -15.5)
  line L59 (10, -12) -> (-10, -12)
  line L60 (12, -15.5) -> (12, -14)
  line L61 (20.8003, -17.5) -> (14, -17.5)
  line L62 (26.0127, -22.5035) -> (22.7506, -18.4359)
  line L63 (57.9246, -10.5) -> (28.969, -23.2281)
  line L64 (67.6263, -10.5) -> (57.9246, -10.5)
  line L65 (73.5, -17.5) -> (67.6263, -10.5)
  line L66 (73.5, -18.5) -> (73.5, -17.5)
  line L67 (81.5, -19.5) -> (74.5, -19.5)
  line L68 (82.5, -17.5) -> (82.5, -18.5)
  line L69 (87.5, -6) -> (82.5, -17.5)
  line L70 (82.5, -1.8045) -> (87.5, -6)
  line L71 (82.5, 1.8045) -> (82.5, -1.8045)
  line L72 (87.5, 6) -> (82.5, 1.8045)
  line L73 (82.5, 17.5) -> (87.5, 6)
  line L74 (82.5, 18.5) -> (82.5, 17.5)
  line L75 (74.5, 19.5) -> (81.5, 19.5)
  line L76 (73.5, 17.5) -> (73.5, 18.5)
  line L77 (67.6263, 10.5) -> (73.5, 17.5)
  line L78 (57.9246, 10.5) -> (67.6263, 10.5)
  line L79 (28.969, 23.2281) -> (57.9246, 10.5)
  line L80 (22.7506, 18.4359) -> (26.0127, 22.5035)
  line L81 (14, 17.5) -> (20.8003, 17.5)
  line L82 (12, 14) -> (12, 15.5)
  line L83 (-10, 12) -> (10, 12)
  line L84 (-12, 15.5) -> (-12, 14)
  line L85 (-20.8003, 17.5) -> (-14, 17.5)
  line L86 (-26.0127, 22.5035) -> (-22.7506, 18.4359)
  line L87 (-57.9246, 10.5) -> (-28.969, 23.2281)
  line L88 (-67.6263, 10.5) -> (-57.9246, 10.5)
  line L89 (74.5928, -92.7456) -> (38.3759, -10.3543)
  line L90 (59.9454, -99.1842) -> (74.5928, -92.7456)
  line L91 (23.7285, -16.7928) -> (59.9454, -99.1842)
  line L92 (38.3759, -10.3543) -> (23.7285, -16.7928)
  curve K1 (75.8051, -115.3838) -> (58.7331, -76.5461)
  curve K2 (75.9644, -92.1427) -> (58.5738, -99.7871)
  circle C1 centre (-77.9376, 16.5656) radius 1.5
  circle C2 centre (77.9376, -16.5656) radius 1.5
  arc A1 centre (20, -5) radius 2 clockwise from (20, -7) to (20, -3)
  arc A2 centre (64.3853, -5) radius 2 clockwise from (64.3853, -3) to (64.3853, -7)
  circle C3 centre (29, -18.845) radius 1.5
  circle C4 centre (36.3237, -15.6258) radius 1.5
  circle C5 centre (15, -15) radius 1.5
  circle C6 centre (15, 15) radius 1.5
  circle C7 centre (36.3237, 15.6258) radius 1.5
  circle C8 centre (29, 18.845) radius 1.5
  arc A3 centre (64.3853, 5) radius 2 clockwise from (64.3853, 7) to (64.3853, 3)
  arc A4 centre (20, 5) radius 2 clockwise from (20, 3) to (20, 7)
  circle C9 centre (77.9376, 16.5656) radius 1.5
  arc A5 centre (-20, 5) radius 2 clockwise from (-20, 7) to (-20, 3)
  arc A6 centre (-64.3853, 5) radius 2 clockwise from (-64.3853, 3) to (-64.3853, 7)
  circle C10 centre (-29, 18.845) radius 1.5
  circle C11 centre (-36.3237, 15.6258) radius 1.5
  circle C12 centre (-15, 15) radius 1.5
  circle C13 centre (-15, -15) radius 1.5
  circle C14 centre (-36.3237, -15.6258) radius 1.5
  circle C15 centre (-29, -18.845) radius 1.5
  arc A7 centre (-64.3853, -5) radius 2 clockwise from (-64.3853, -7) to (-64.3853, -3)
  arc A8 centre (-20, -5) radius 2 clockwise from (-20, -3) to (-20, -7)
  arc A9 centre (-74.5, 18.5) radius 1 clockwise from (-74.5, 19.5) to (-73.5, 18.5)
  arc A10 centre (-81.5, 18.5) radius 1 clockwise from (-82.5, 18.5) to (-81.5, 19.5)
  arc A11 centre (-81.5, -18.5) radius 1 clockwise from (-81.5, -19.5) to (-82.5, -18.5)
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  point P175 (67.2691, -95.9649)
  point P33 (29, -18.845)
  point P34 (36.3237, -15.6258)
  point P171 (38.3759, -10.3543)
  point P172 (74.5928, -92.7456)
  perpendicular L89 L90
  parallel L89 L91
  parallel L90 L92
  perpendicular L63 L89
  midpoint L90 P175
  perpendicular L90 K1
  dimension "d88" distance P33 L91 = 4
  dimension "d89" distance P34 L89 = 4
  dimension "d90" distance P34 L92 = 4
  dimension "d91" distance P171 P172 = 90
extrude "拉伸15" new body sketch "草图13" along normal blind 4.5
fillet "圆角6" radius 2.5
sketch "草图14" plane through (0, -4.5, 0) normal (0, -1, 0) x axis (1, 0, 0)
  line L1 (55.3439, -88.7159) -> (24.7345, -19.0815)
  line L2 (39.3819, -12.6429) -> (69.9912, -82.2774)
  line L3 (26.0172, -15.7868) -> (36.0872, -11.3603)
  line L4 (42.8018, -28.354) -> (42.8018, -20.4229)
  line L5 (63.4692, -75.3713) -> (42.8018, -28.354)
  line L6 (69.3127, -80.7337) -> (63.4692, -75.3713)
  line L7 (43.9716, -42.9644) -> (31.0522, -13.5736)
  line L8 (54.6653, -79.2412) -> (33.9979, -32.2239)
  line L9 (54.6653, -87.1723) -> (54.6653, -79.2412)
  line L10 (33.9979, -32.2239) -> (28.1544, -26.8615)
  arc A1 centre (27.0232, -18.0755) radius 2.5 clockwise from (24.7345, -19.0815) to (26.0172, -15.7868)
  closed curve K1 centre (67.2691, -95.9649)
  arc A2 centre (37.0933, -13.649) radius 2.5 clockwise from (36.0872, -11.3603) to (39.3819, -12.6429)
  circle C1 centre (36.3237, -15.6258) radius 1.5
  circle C2 centre (29, -18.845) radius 1.5
  point P13 (42.8018, -20.4229)
  point P16 (69.3127, -80.7337)
  point P17 (31.0522, -13.5736)
  point P22 (28.1544, -26.8615)
  point P14 (42.8018, -28.354)
  point P19 (33.9979, -32.2239)
  point P15 (63.4692, -75.3713)
  point P20 (54.6653, -79.2412)
  point P21 (54.6653, -87.1723)
  coincident L2 P13
  vertical L4
  parallel L2 L5
  coincident L2 P16
  equal L4 L6
  midpoint L3 P17
  perpendicular L3 L7
  symmetric P13 L7 P22
  symmetric P14 L7 P19
  symmetric P15 L7 P20
  symmetric P16 L7 P21
extrude "拉伸16" cut sketch "草图14" profile of L1 L2 L4 L5 L6 L8 L9 L10 against normal blind 17
sketch "草图15" plane through (0, -4.5, 0) normal (0, -1, 0) x axis (1, 0, 0)
  line L1 (63.4692, -75.3713) -> (69.3127, -80.7337)
  line L2 (42.8018, -28.354) -> (63.4692, -75.3713)
  line L3 (42.8018, -20.4229) -> (42.8018, -28.354)
  line L4 (39.3819, -12.6429) -> (42.8018, -20.4229)
  line L5 (26.0172, -15.7868) -> (36.0872, -11.3603)
  line L6 (28.1544, -26.8615) -> (24.7345, -19.0815)
  line L7 (33.9979, -32.2239) -> (28.1544, -26.8615)
  line L8 (54.6653, -79.2412) -> (33.9979, -32.2239)
  line L9 (54.6653, -87.1723) -> (54.6653, -79.2412)
  line L10 (55.3439, -88.7159) -> (54.6653, -87.1723)
  line L11 (69.3127, -80.7337) -> (69.9912, -82.2774)
  line L12 (70.0909, -88.7166) -> (60.0208, -93.1432)
  line L13 (74.5174, -98.7867) -> (70.0909, -88.7166)
  line L14 (64.4473, -103.2132) -> (74.5174, -98.7867)
  line L15 (60.0208, -93.1432) -> (64.4473, -103.2132)
  circle C1 centre (29, -18.845) radius 1.5
  circle C2 centre (36.3237, -15.6258) radius 1.5
  arc A1 centre (37.0933, -13.649) radius 2.5 clockwise from (36.0872, -11.3603) to (39.3819, -12.6429)
  arc A2 centre (27.0232, -18.0755) radius 2.5 clockwise from (24.7345, -19.0815) to (26.0172, -15.7868)
  closed curve K1 centre (67.2691, -95.9649)
  circle C3 centre (67.2691, -95.9649) radius 5.5
  circle C4 centre (70.0909, -88.7166) radius 2
  circle C5 centre (67.2691, -95.9649) radius 4
  point P23 (70.0909, -88.7166)
  point P26 (70.0909, -88.7166)
  concentric K1 C3
  perpendicular L12 L13
  parallel L12 L14
  parallel L13 L15
  tangent C3 L12
  tangent C3 L13
  tangent C3 L14
  tangent C3 L15
  parallel L2 L13
  coincident P23 P26
  concentric C3 C5
  dimension "d98" diameter C3 = 11
  dimension "d99" diameter C4 = 4
  dimension "d100" diameter C5 = 8
extrude "拉伸17" cut sketch "草图15" profile of C4 C5 against normal blind 9
circular_pattern "C-阵列1" TotalAngle 360
sketch "草图16" plane through (0, -4.5, 0) normal (0, -1, 0) x axis (1, 0, 0)
  line L1 (63.4692, -75.3713) -> (69.3127, -80.7337)
  line L2 (42.8018, -28.354) -> (63.4692, -75.3713)
  line L3 (42.8018, -20.4229) -> (42.8018, -28.354)
  line L4 (39.3819, -12.6429) -> (42.8018, -20.4229)
  line L5 (26.0172, -15.7868) -> (36.0872, -11.3603)
  line L6 (28.1544, -26.8615) -> (24.7345, -19.0815)
  line L7 (33.9979, -32.2239) -> (28.1544, -26.8615)
  line L8 (54.6653, -79.2412) -> (33.9979, -32.2239)
  line L9 (54.6653, -87.1723) -> (54.6653, -79.2412)
  line L10 (55.3439, -88.7159) -> (54.6653, -87.1723)
  line L11 (69.3127, -80.7337) -> (69.9912, -82.2774)
  line L12 (72.9991, -109.0004) -> (67.2691, -95.9649)
  circle C1 centre (60.0208, -93.1432) radius 2
  circle C2 centre (64.4473, -103.2132) radius 2
  circle C3 centre (74.5174, -98.7867) radius 2
  circle C4 centre (70.0909, -88.7166) radius 2
  circle C5 centre (67.2691, -95.9649) radius 4
  circle C6 centre (29, -18.845) radius 1.5
  circle C7 centre (36.3237, -15.6258) radius 1.5
  arc A1 centre (37.0933, -13.649) radius 2.5 clockwise from (36.0872, -11.3603) to (39.3819, -12.6429)
  arc A2 centre (27.0232, -18.0755) radius 2.5 clockwise from (24.7345, -19.0815) to (26.0172, -15.7868)
  closed curve K1 centre (67.2691, -95.9649)
  circle C8 centre (75.8051, -115.3838) radius 10
  point P25 (75.8051, -115.3838)
  point P6 (67.2691, -95.9649)
  point P26 (67.2691, -95.9649)
  coincident K1 P25
  coincident P6 P26
  parallel L2 L12
  coincident P25 L12
  dimension "d105" diameter C8 = 20
extrude "拉伸18" cut sketch "草图16" profile of K1 C8 against normal blind 15
fillet "圆角7" radius 3
mirror "镜像5" mirrorStitchTolerance 0.1
mirror "镜像6" mirrorStitchTolerance 0.1
sketch "草图1" plane through (0, 0, 0) normal (0, 1, 0) x axis (1, 0, 0)
  line L1 (-7.4953, -7.4953) -> (7.4953, 7.4953)
  line L2 (31.5785, 7.4953) -> (7.4953, 7.4953)
  circle C1 centre (0, 0) radius 6
  circle C2 centre (5.3033, 5.3033) radius 3.1
  circle C3 centre (-5.3033, 5.3033) radius 3.1
  circle C4 centre (-5.3033, -5.3033) radius 3.1
  circle C5 centre (5.3033, -5.3033) radius 3.1
  point P1 (0, 0)
  point P2 (0, 0)
  point P6 (0, 0)
  point P10 (5.3033, 5.3033)
  point P3 (7.4953, 7.4953)
  point P4 (-7.4953, -7.4953)
  coincident P1 P2
  horizontal L2
  coincident P2 L1
  midpoint L1 P6
  coincident P2 P6
  coincident L1 P10
  coincident P3 C2
  dimension "d1_1" diameter C1 = 12
  dimension "d2_1" angle L1 L2 = 135
  dimension "d3_1" distance P3 P4 = 21.2
  dimension "d4_1" diameter C2 = 6.2
  dimension "d6_1" C-Pattern1-Angle = 360
extrude "拉伸1" new body sketch "草图1" profile of C1 C2 C3 C4 C5 along normal blind 2.2 named "d7_1"
sketch "草图2" plane through (0, 2.2, 0) normal (0, 1, 0) x axis (-1, 0, 0)
  arc A1 centre (-5.3033, 5.3033) radius 3.1 clockwise from (-5.5761, 2.2153) to (-2.2153, 5.5761)
  arc A2 centre (0, 0) radius 6 clockwise from (-5.5761, -2.2153) to (-5.5761, 2.2153)
  arc A3 centre (-5.3033, -5.3033) radius 3.1 clockwise from (-2.2153, -5.5761) to (-5.5761, -2.2153)
  arc A4 centre (0, 0) radius 6 clockwise from (2.2153, -5.5761) to (-2.2153, -5.5761)
  arc A5 centre (5.3033, -5.3033) radius 3.1 clockwise from (5.5761, -2.2153) to (2.2153, -5.5761)
  arc A6 centre (0, 0) radius 6 clockwise from (5.5761, 2.2153) to (5.5761, -2.2153)
  arc A7 centre (5.3033, 5.3033) radius 3.1 clockwise from (2.2153, 5.5761) to (5.5761, 2.2153)
  arc A8 centre (0, 0) radius 6 clockwise from (-2.2153, 5.5761) to (2.2153, 5.5761)
extrude "拉伸2" cut sketch "草图1" profile of C1 C2 C3 C4 C5 along normal blind 0.2 named "d9_1"
sketch "草图3" plane through (0, 2.2, 0) normal (0, 1, 0) x axis (-1, 0, 0)
  circle C1 centre (0, 0) radius 6
  point P1 (0, 0)
  point P2 (0, 0)
  point P3 (2.2153, 5.5761)
  coincident P1 P2
  coincident C1 P3
extrude "拉伸3" add sketch "草图3" along normal blind 3 named "d11_1"
sketch "草图4" plane through (0, 5.2, 0) normal (0, 1, 0) x axis (-1, 0, 0)
  circle C1 centre (0, 0) radius 6
  circle C2 centre (0, 0) radius 14
  concentric C1 C2
  dimension "d13_1" diameter C2 = 28
extrude "拉伸4" add sketch "草图4" along normal blind 12 named "d14_1"
hole "孔" HoleDepth 3 named "d16_1" HoleDiameter 1.623 named "d17_1" TipAngle 118 named "d18_1"
circular_pattern "C-阵列1" TotalAngle 360 named "d20_1"
sketch "草图5" plane through (0, 17.2, 0) normal (0, 1, 0) x axis (-1, 0, 0)
  circle C1 centre (0, 0) radius 14
  circle C2 centre (0, 0) radius 2
  point P1 (0, 0)
  point P3 (0, 0)
  coincident P1 P3
  dimension "d21_1" diameter C2 = 4
extrude "拉伸5" add sketch "草图5" profile of C2 along normal blind 13 named "d22_1"
chamfer "倒角1" distance 0.5 named "d24_1"
thread "螺纹2" ThreadOffset 0 named "d25_1" ThreadLength 10 named "d26_1"
sketch "草图6" plane through (0, 17.2, 0) normal (0, 1, 0) x axis (-1, 0, 0)
  circle C1 centre (0, 0) radius 1.954
  circle C2 centre (0, 0) radius 13.5
  circle C3 centre (0, 0) radius 4.5
  circle C4 centre (0, 0) radius 2
  point P1 (0, 0)
  point P3 (0, 0)
  coincident P1 P3
  concentric C1 C4
  dimension "d27_1" diameter C3 = 9
  dimension "d28_1" diameter C4 = 4
extrude "拉伸1" new body sketch "草图6" profile of C3 C4 along normal blind 6.5 named "d29_1"
sketch "草图7" plane through (0, 0, 0) normal (0, 0, 1) x axis (1, 0, 0)
  line L1 (-4.5, 23.7) -> (4.5, 23.7)
  line L2 (-4.5, 18.5) -> (-4.5, 19.2)
  line L3 (4.3302, 23.7) -> (4, 23.7)
  arc A1 centre (-4.0652, 28.6565) radius 9.4665 clockwise from (4, 23.7) to (-4.5, 19.2)
  arc A2 centre (-7.0212, 28.7498) radius 12.424 clockwise from (4.3302, 23.7) to (0, 18.5)
  arc A3 centre (-2.25, 22.0439) radius 4.1978 clockwise from (0, 18.5) to (-4.5, 18.5)
  point P2 (4, 23.7)
  point P7 (4.3302, 23.7)
  coincident P2 L1
  tangent A1 A2
  coincident L1 P7
  vertical L2
emboss "凸雕" sketch "草图7" Depth 58 named "d31_1" Horizontal Distance 0 named "d32_1" Vertical Distance 0 named "d33_1" Rotation Angle 0 named "d34_1"
sketch "草图8" plane through (0, 23.7, 0) normal (0, 1, 0) x axis (-1, 0, 0)
  line L1 (-48.5232, 39.3922) -> (-3.4937, 2.8362)
  line L2 (-3.6922, 2.5725) -> (-51.2807, 35.7287)
  line L3 (-6, 14) -> (-3.25, 3.1125)
  line L4 (-1.3471, 61.1563) -> (-6.2919, 18.4076)
  curve K1 (-3.4937, 2.8362) -> (3.7866, 2.4314)
  line L5 (52.5919, 33.7689) -> (3.7866, 2.4314)
  curve K2 (-48.5232, 39.3922) -> (52.5919, 33.7689)
  line L6 (-3.4937, 2.8362) -> (-48.5232, 39.3922)
  circle C1 centre (0, 0) radius 2
  arc A1 centre (0, 0) radius 4.5 clockwise from (-3.4937, 2.8362) to (-3.6922, 2.5725)
  arc A2 centre (0, 0) radius 62.5 clockwise from (-51.2807, 35.7287) to (-48.5232, 39.3922)
  circle C2 centre (0, 0) radius 4.5
  arc A3 centre (5.8773, 17) radius 12.2503 clockwise from (-6, 14) to (-6.2919, 18.4076)
  arc A4 centre (0.0347, 61.0069) radius 1.3898 clockwise from (-1.3471, 61.1563) to (1.4243, 61.0272)
  arc A5 centre (275.4798, 65.0306) radius 274.0847 clockwise from (6, 15) to (1.4243, 61.0272)
  arc A6 centre (-2.1744, 13.4824) radius 8.3141 clockwise from (6, 15) to (4.4726, 8.4882)
  arc A7 centre (9.8683, 4.4342) radius 6.749 clockwise from (3.25, 3.1125) to (4.4726, 8.4882)
  point P8 (-3.25, 3.1125)
  point P9 (3.25, 3.1125)
  point P10 (-3.25, 3.1125)
  point P25 (3.25, 3.1125)
  concentric C1 C2
  coincident A1 P8
  coincident C2 P8
  coincident A1 P9
  horizontal P8 P9
  coincident P8 P10
  tangent L3 A3
  tangent A3 L4
  coincident P9 P25
  tangent A6 A7
  tangent A5 A6
  tangent A4 A5
  dimension "d35_1" diameter C2 = 9
  dimension "d36_1" distance P8 P9 = 6.5
extrude "拉伸2" sketch "草图8" profile of A1 C2 L3 A3 L4 A4 A5 A6 A7 against normal blind 18
extrude "拉伸6" new body sketch "草图8" profile of C1 A1 C2 K1 against normal blind 6.5 named "d39_1"
combine "合并1"
sketch "草图9" plane through (0, 23.7, 0) normal (0, 1, 0) x axis (-1, 0, 0)
  curve K1 (-4.3555, -1.1312) -> (-3.9989, 2.0636)
  curve K2 (-2.7216, -3.5837) -> (-4.3555, -1.1312)
  curve K3 (-0.7094, -4.4437) -> (-2.7216, -3.5837)
  circle C1 centre (0, 0) radius 2
  arc A1 centre (0, 0) radius 4.5 clockwise from (-3.9989, 2.0636) to (-0.7094, -4.4437)
  circle C2 centre (0, 0) radius 4.25
  circle C3 centre (0, 0) radius 2.1
  point P1 (0, 0)
  point P7 (0, 0)
  point P8 (0, 0)
  coincident P1 P7
  coincident P1 P8
  dimension "d43_1" diameter C2 = 8.5
  dimension "d44_1" diameter C3 = 4.2
extrude "拉伸7" new body sketch "草图9" profile of C2 C3 along normal blind 1 named "d45_1"
chamfer "倒角2" distance 0.5 named "d47_1"
sketch "草图10" plane through (0, 24.7, 0) normal (0, 1, 0) x axis (-1, 0, 0)
  line L1 (3.75, 0) -> (1.875, -3.2476)
  line L2 (1.875, 3.2476) -> (3.75, 0)
  line L3 (-1.875, 3.2476) -> (1.875, 3.2476)
  line L4 (-3.75, 0) -> (-1.875, 3.2476)
  line L5 (-1.875, -3.2476) -> (-3.75, 0)
  line L6 (1.875, -3.2476) -> (-1.875, -3.2476)
  circle C1 centre (0, 0) radius 2.1
  circle C2 centre (0, 0) radius 3.75
  point P1 (0, 0)
  point P9 (0, 0)
  point P8 (-1.875, -3.2476)
  coincident P1 P9
  coincident C2 P8
extrude "拉伸8" add sketch "草图10" profile of C1 L1 L2 L3 L4 L5 L6 along normal blind 4 named "d48_1"
sketch "草图11" plane through (0, 28.7, 0) normal (0, 1, 0) x axis (-1, 0, 0)
  line L1 (1.875, -3.2476) -> (-1.875, -3.2476)
  line L2 (3.75, 0) -> (1.875, -3.2476)
  line L3 (1.875, 3.2476) -> (3.75, 0)
  line L4 (-1.875, 3.2476) -> (1.875, 3.2476)
  line L5 (-3.75, 0) -> (-1.875, 3.2476)
  line L6 (-1.875, -3.2476) -> (-3.75, 0)
  circle C1 centre (0, 0) radius 2.1
  circle C2 centre (0, 0) radius 2.9155
  circle C3 centre (0, 0) radius 2.1
  concentric C1 C2
  concentric C2 C3
extrude "拉伸9" add sketch "草图11" profile of C1 C2 C3 along normal blind 1.5 named "d50_1"
fillet "圆角1" radius 0.5 named "d53_1"
copy_paste_bodies "复制和粘贴实体"
move "移动1"
circular_pattern "C-阵列2" TotalAngle 360 named "d55_1"
combine "合并1"
remove_instance "移除实例1"
joint "装配1" alignAngle 180 alignOffsetX 0 alignOffsetY 0 alignOffsetZ 0
mirror_component "镜像零部件1"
